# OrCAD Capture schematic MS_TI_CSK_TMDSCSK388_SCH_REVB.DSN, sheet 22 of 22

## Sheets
22 11.DM388 I/O PERIPHERALS: size C; title: DM388 I/O PERIPHERALS
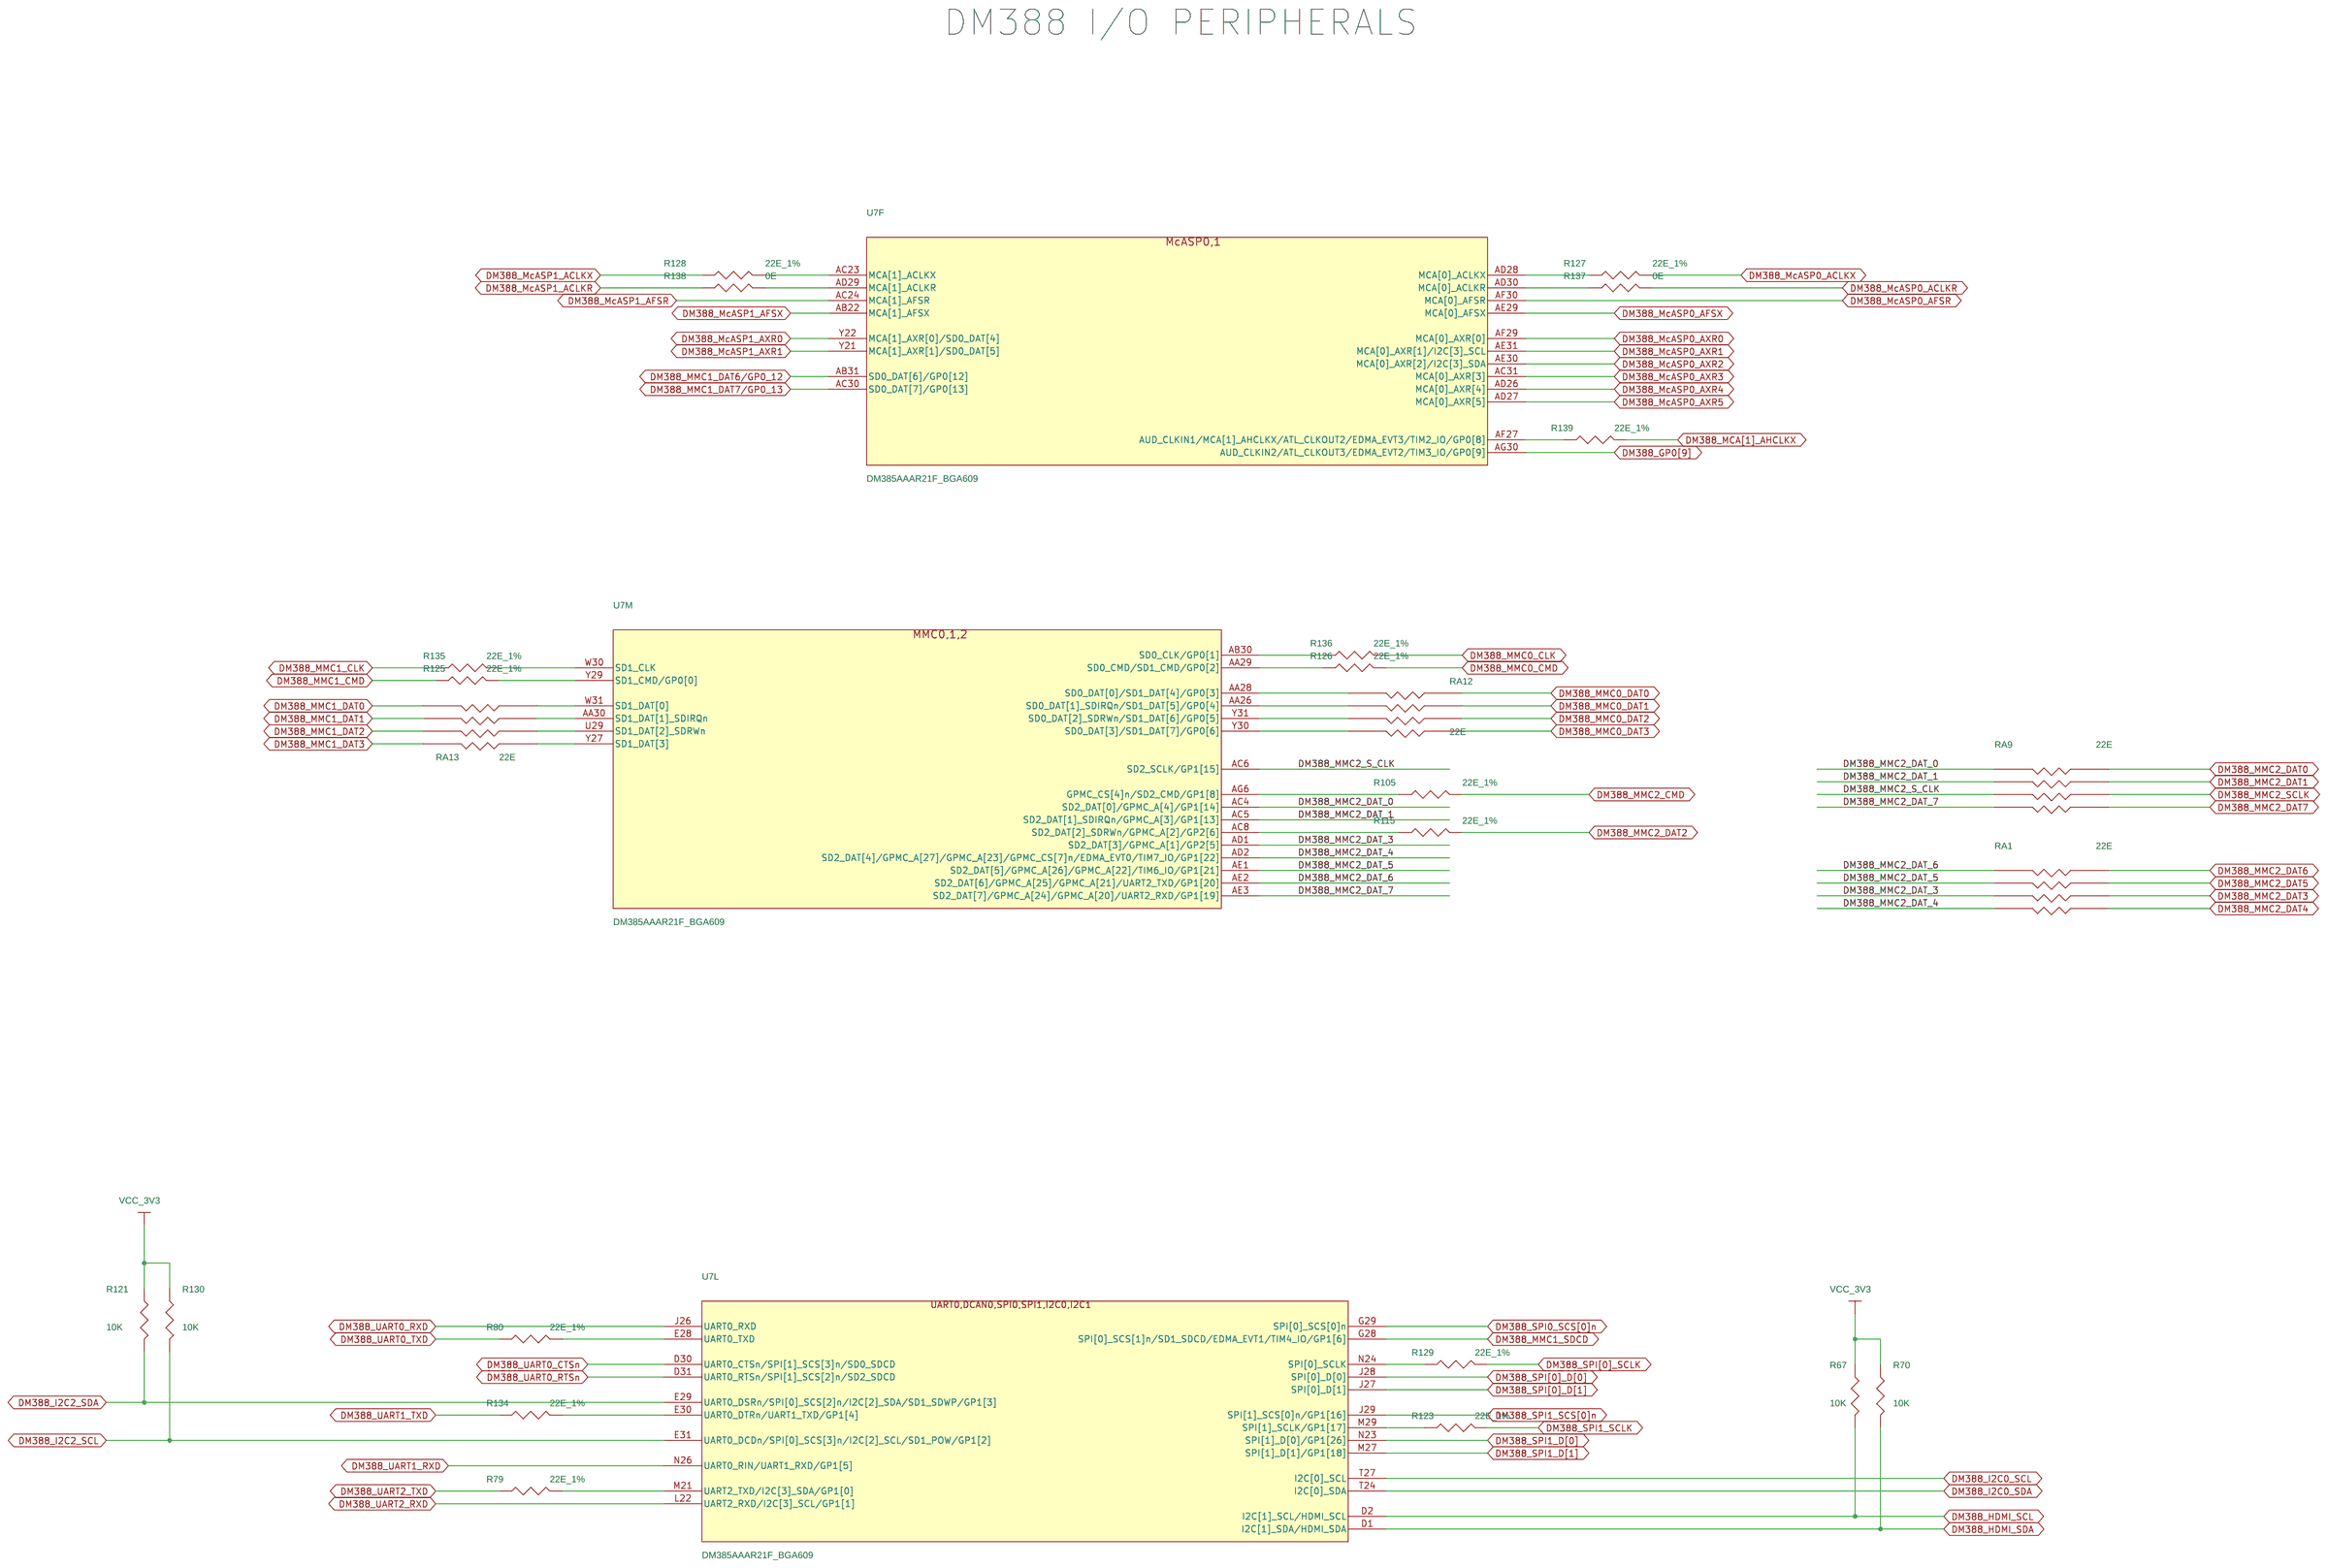
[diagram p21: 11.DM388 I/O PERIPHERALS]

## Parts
sheet 11.DM388 I/O PERIPHERALS
R67  10K  [RES0402]
R70  10K  [RES0402]
R79  22E_1%  [RES0402]
R80  22E_1%  [RES0402]
R105  22E_1%  [RES0402]
R115  22E_1%  [RES0402]
R121  10K  [RES0402]
R123  22E_1%  [RES0402]
R125  22E_1%  [RES0402]
R126  22E_1%  [RES0402]
R127  22E_1%  [RES0402]
R128  22E_1%  [RES0402]
R129  22E_1%  [RES0402]
R130  10K  [RES0402]
R134  22E_1%  [RES0402]
R135  22E_1%  [RES0402]
R136  22E_1%  [RES0402]
R137  0E  [RES0402]
R138  0E  [RES0402]
R139  22E_1%  [RES0402]
RA1  22E  [RESA_741X083_0402-4]
RA9  22E  [RESA_741X083_0402-4]
RA12  22E  [RESA_741X083_0402-4]
RA13  22E  [RESA_741X083_0402-4]
sheet 19.ETHERNET,HDMI & USB
U7  DM388AAAR21FP  [BGA609_19-68_635X635]  (sections A,B,C,D,E,F,G,H,I,J,K,L,M,N)

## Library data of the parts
R67 R70 R121 R130 = RESISTOR: RES 10K 1/16W 5% 0402; Alternate_mfr_name_A: AVX CORPORATION; Alternate_mfr_name_B: PANASONIC-ECG-ECG; Alternate_mfr_name_C: YAGEO AMERICA; Alternate_mfr_name_D: WALSIN; Alternate_mfr_part_number_A: CR05-103J-H; Alternate_mfr_part_number_B: ERJ-2GEJ103X; Alternate_mfr_part_number_C: 9C04021A1002JLHF3; Alternate_mfr_part_number_D: WR04X103_JT; Chkd/date: SHREESHAIL/061205; Crtd /date: MAZHAR/230805; Custom_Duty: 15%; Customs_HS_Code: 85332119; Distributor_name: DIGIKEY; Distributor_name_A: MOUSER; Distributor_name_B: DIGIKEY; Distributor_name_C: DIGIKEY; Distributor_name_D: NA; Distributor_part_number: 311-10KJRCT-ND; Distributor_part_number_A: 581-CR051002JT; Distributor_part_number_B: P10KJCT-ND; Distributor_part_number_C: 311-10KJCT-ND; Distributor_part_number_D: NA; Height: 0.40MM; Mfr_name: YAGEO AMERICA; Mfr_part_number: RC0402JR-0710KL; Mistral Part No: 110009030208-P; Package: 0402; Part_type: RESISTORS\FIXED; Project: HSE; RoHS: Pb-Free; Tolerance: 5%; Wattage: 1/16W; Datasheet: Y:\MIS_DATABASE\DATASHEETS\RESISTORS\YAGEO-RC0402.PDF
R79 R80 R105 R115 R123 R125-R129 R134-R136 R139 = RESISTOR: RES 22E 1/16W 1% 0402; Alternate_mfr_name_A: VISHAY; Alternate_mfr_part_number_A: CRCW040222R0FKED; Chkd/date: SUHAS/290910; Crtd /date: MAZHAR/090909; Cust_part_number: 4700-80047E; Custom_Duty: 15%; Customs_HS_Code: 85332119; Distributor_name: DIGIKEY; Distributor_name_A: DIGIKEY; Distributor_part_number: 311-22.0LRCT-ND; Distributor_part_number_A: 541-22.0LCT-ND; Height: 0.40MM; Mfr_name: YAGEO AMERICA; Mfr_part_number: RC0402FR-0722RL; Mistral Part No: 110009090004-P; Package: 0402; Part_type: RESISTORS\FIXED; Project: VMEFMCD; Remarks: In alternate datasheet it is RoHS COMPLIANT. Y:\MIS_DATABASE\DATASHEETS\RESISTORS\CRCW0402.PDF; RoHS: Pb-Free; Temperature: -55°C+155°C; Tolerance: 1%; Voltage: 50V; Wattage: 1/16W; Weight: 0.8g/1000pcs; Datasheet: Y:\MIS_DATABASE\DATASHEETS\RESISTORS\YAGEO-RC0402.PDF
R137 R138 = RESISTOR: RES 0K 1/16W 5% 0402; Chkd/date: USMAN240712; Crtd /date: CHAITHANYA/300911; Custom_Duty: 15%; Customs_HS_Code: 85332119; Distributor_name: DIGIKEY; Distributor_part_number: 311-0.0JRCT-ND; Height: 0.40MM; Mfr_name: YAGEO; Mfr_part_number: RC0402JR-070RL; Mistral Part No: 110011090036-R; Package: 0402; Part_type: RESISTORS\FIXED; Project: VP-4000-PROCESSOR; RoHS: RoHS; SIGNAL_MODEL: RESISTOR_RES0402_0E_0E; Temperature: -55°C+155°C; Tolerance: 5%; Voltage: NA; Wattage: 1/16W; Weight: NA; Datasheet: Y:\MIS_DATABASE\DATASHEETS\RESISTORS\YAGEO_RC0402JR.PDF
RA1 RA9 RA12 RA13 = RESARR_ISO4: RES ARRAY 4RES 22E 62.5mW 5% 0402; Chkd/date: VASANTHA/130516; Crtd /date: VASANTHA/130516; Distributor_name: DIGIKEY; Distributor_part_number: 741X083220JPCT-ND; Height: 0.50MM; Mfr_name: CTS; Mfr_part_number: 741X083220JP; Mistral Part No: 110016050004-R; Package: 0402; Part_type: RESISTORS\ARRAY; Project: TMDXCSK368; RoHS: RoHS; Temperature: -55°C+125°C; Tolerance: 5%; Voltage: NA; Wattage: 62.5mW; Weight: NA; Datasheet: Y:\MIS_DATABASE\DATASHEETS\RESISTORS\741C083.PDF
U7 = DM385AAAR21F_BGA609: IC PROCESSOR DIGITAL MEDIA FCBGA609; Chkd/date: VASANTHA/170516; Color: Default; Crtd /date: VASANTHA/170516; Custom_Duty: 15%; Customs_HS_Code: 85423100; Distributor_name: NA; Distributor_part_number: NA; Height: 1.32MM; Location X-Coordinate: 0; Location Y-Coordinate: 0; Mfr_name: TEXAS INSTRUMENTS; Mistral Part No: 141216050002-R; Package: FCBGA609; Part_type: ICS\DIGITAL\MICROPROCESSOR; Power Pins Visible: False; Primitive: DEFAULT; Project: TMDXCSK388; RoHS: RoHS; Temperature: 0°C+95°C; Tolerance: NA; Voltage: NA; Wattage: NA; Weight: NA; Datasheet: Y:\MIS_DATABASE\DATASHEETS\ICS\DIGITAL\MICROCONTROLLER\DM385-88.PDF

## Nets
VCC_3V3: R67.1 R70.1 R121.1 R130.1 ; also on sheet 9 10 12 13 14 16 17 18 19 21
DM388_GP0[9]: U7.AG30(AUD_CLKIN2/ATL_CLKOUT3/EDMA_EVT2/TIM3_IO/GP0[9]) ; also on sheet 21
DM388_HDMI_SCL: R67.2 U7.D2(I2C[1]_SCL/HDMI_SCL) ; also on sheet 21
DM388_HDMI_SDA: R70.2 U7.D1(I2C[1]_SDA/HDMI_SDA) ; also on sheet 21
DM388_I2C0_SCL: U7.T27(I2C[0]_SCL) ; also on sheet 17
DM388_I2C0_SDA: U7.T24(I2C[0]_SDA) ; also on sheet 17
DM388_I2C2_SCL: R130.2 U7.E31(UART0_DCDn/SPI[0]_SCS[3]n/I2C[2]_SCL/SD1_POW/GP1[2]) ; also on sheet 21
DM388_I2C2_SDA: R121.2 U7.E29(UART0_DSRn/SPI[0]_SCS[2]n/I2C[2]_SDA/SD1_SDWP/GP1[3]) ; also on sheet 21
DM388_MCA[1]_AHCLKX: R139.2 ; also on sheet 21
DM388_McASP0_ACLKR: R137.2 ; also on sheet 21
DM388_McASP0_ACLKX: R127.2 ; also on sheet 12
DM388_McASP0_AFSR: U7.AF30(MCA[0]_AFSR) ; also on sheet 21
DM388_McASP0_AFSX: U7.AE29(MCA[0]_AFSX) ; also on sheet 12
DM388_McASP0_AXR0: U7.AF29(MCA[0]_AXR[0]) ; also on sheet 12
DM388_McASP0_AXR1: U7.AE31(MCA[0]_AXR[1]/I2C[3]_SCL) ; also on sheet 12
DM388_McASP0_AXR2: U7.AE30(MCA[0]_AXR[2]/I2C[3]_SDA) ; also on sheet 21
DM388_McASP0_AXR3: U7.AC31(MCA[0]_AXR[3]) ; also on sheet 21
DM388_McASP0_AXR4: U7.AD26(MCA[0]_AXR[4]) ; also on sheet 21
DM388_McASP0_AXR5: U7.AD27(MCA[0]_AXR[5]) ; also on sheet 21
DM388_McASP1_ACLKR: R138.1 ; also on sheet 21
DM388_McASP1_ACLKX: R128.1 ; also on sheet 21
DM388_McASP1_AFSR: U7.AC24(MCA[1]_AFSR) ; also on sheet 21
DM388_McASP1_AFSX: U7.AB22(MCA[1]_AFSX) ; also on sheet 21
DM388_McASP1_AXR0: U7.Y22(MCA[1]_AXR[0]/SD0_DAT[4]) ; also on sheet 21
DM388_McASP1_AXR1: U7.Y21(MCA[1]_AXR[1]/SD0_DAT[5]) ; also on sheet 21
DM388_MMC0_CLK: R136.2 ; also on sheet 12
DM388_MMC0_CMD: R126.2 ; also on sheet 12
DM388_MMC0_DAT0: RA12.4 ; also on sheet 12
DM388_MMC0_DAT1: RA12.3 ; also on sheet 12
DM388_MMC0_DAT2: RA12.2 ; also on sheet 12
DM388_MMC0_DAT3: RA12.1 ; also on sheet 12
DM388_MMC1_CLK: R135.1 ; also on sheet 21
DM388_MMC1_CMD: R125.1 ; also on sheet 21
DM388_MMC1_DAT0: RA13.5 ; also on sheet 21
DM388_MMC1_DAT1: RA13.6 ; also on sheet 21
DM388_MMC1_DAT2: RA13.7 ; also on sheet 21
DM388_MMC1_DAT3: RA13.8 ; also on sheet 21
DM388_MMC1_DAT6/GP0_12: U7.AB31(SD0_DAT[6]/GP0[12]) ; also on sheet 21
DM388_MMC1_DAT7/GP0_13: U7.AC30(SD0_DAT[7]/GP0[13]) ; also on sheet 21
DM388_MMC1_SDCD: U7.G28(SPI[0]_SCS[1]n/SD1_SDCD/EDMA_EVT1/TIM4_IO/GP1[6]) ; also on sheet 21
DM388_MMC2_CMD: R105.2 ; also on sheet 21
DM388_MMC2_DAT0: RA9.4 ; also on sheet 21
DM388_MMC2_DAT1: RA9.3 ; also on sheet 21
DM388_MMC2_DAT2: R115.2 ; also on sheet 21
DM388_MMC2_DAT3: RA1.2 ; also on sheet 21
DM388_MMC2_DAT4: RA1.1 ; also on sheet 21
DM388_MMC2_DAT5: RA1.3 ; also on sheet 21
DM388_MMC2_DAT6: RA1.4 ; also on sheet 21
DM388_MMC2_DAT7: RA9.1 ; also on sheet 21
DM388_MMC2_DAT_0: RA9.5 U7.AC4(SD2_DAT[0]/GPMC_A[4]/GP1[14])
DM388_MMC2_DAT_1: RA9.6 U7.AC5(SD2_DAT[1]_SDIRQn/GPMC_A[3]/GP1[13])
DM388_MMC2_DAT_3: RA1.7 U7.AD1(SD2_DAT[3]/GPMC_A[1]/GP2[5])
DM388_MMC2_DAT_4: RA1.8 U7.AD2(SD2_DAT[4]/GPMC_A[27]/GPMC_A[23]/GPMC_CS[7]n/EDMA_EVT0/TIM7_IO/GP1[22])
DM388_MMC2_DAT_5: RA1.6 U7.AE1(SD2_DAT[5]/GPMC_A[26]/GPMC_A[22]/TIM6_IO/GP1[21])
DM388_MMC2_DAT_6: RA1.5 U7.AE2(SD2_DAT[6]/GPMC_A[25]/GPMC_A[21]/UART2_TXD/GP1[20])
DM388_MMC2_DAT_7: RA9.8 U7.AE3(SD2_DAT[7]/GPMC_A[24]/GPMC_A[20]/UART2_RXD/GP1[19])
DM388_MMC2_S_CLK: RA9.7 U7.AC6(SD2_SCLK/GP1[15])
DM388_MMC2_SCLK: RA9.2 ; also on sheet 21
DM388_SPI0_SCS[0]n: U7.G29(SPI[0]_SCS[0]n) ; also on sheet 21
DM388_SPI1_D[0]: U7.N23(SPI[1]_D[0]/GP1[26]) ; also on sheet 21
DM388_SPI1_D[1]: U7.M27(SPI[1]_D[1]/GP1[18]) ; also on sheet 21
DM388_SPI1_SCLK: R123.2 ; also on sheet 21
DM388_SPI1_SCS[0]n: U7.J29(SPI[1]_SCS[0]n/GP1[16]) ; also on sheet 21
DM388_SPI[0]_D[0]: U7.J28(SPI[0]_D[0]) ; also on sheet 21
DM388_SPI[0]_D[1]: U7.J27(SPI[0]_D[1]) ; also on sheet 21
DM388_SPI[0]_SCLK: R129.2 ; also on sheet 21
DM388_UART0_CTSn: U7.D30(UART0_CTSn/SPI[1]_SCS[3]n/SD0_SDCD) ; also on sheet 21
DM388_UART0_RTSn: U7.D31(UART0_RTSn/SPI[1]_SCS[2]n/SD2_SDCD) ; also on sheet 21
DM388_UART0_RXD: U7.J26(UART0_RXD) ; also on sheet 21
DM388_UART0_TXD: R80.1 ; also on sheet 21
DM388_UART1_RXD: U7.N26(UART0_RIN/UART1_RXD/GP1[5]) ; also on sheet 21
DM388_UART1_TXD: R134.1 ; also on sheet 21
DM388_UART2_RXD: U7.L22(UART2_RXD/I2C[3]_SCL/GP1[1]) ; also on sheet 12
DM388_UART2_TXD: R79.1 ; also on sheet 12
N14567220: R136.1 U7.AB30(SD0_CLK/GP0[1])
N14567296: R135.2 U7.W30(SD1_CLK)
N14568444: R127.1 U7.AD28(MCA[0]_ACLKX)
N14568464: R128.2 U7.AC23(MCA[1]_ACLKX)
N14568476: R139.1 U7.AF27(AUD_CLKIN1/MCA[1]_AHCLKX/ATL_CLKOUT2/EDMA_EVT3/TIM2_IO/GP0[8])
N14776629: R138.2 U7.AD29(MCA[1]_ACLKR)
N14776712: R137.1 U7.AD30(MCA[0]_ACLKR)
N14776785: R129.1 U7.N24(SPI[0]_SCLK)
N14776789: R123.1 U7.M29(SPI[1]_SCLK/GP1[17])
N14783196: RA13.4 U7.W31(SD1_DAT[0])
N14783200: RA13.3 U7.AA30(SD1_DAT[1]_SDIRQn)
N14783204: RA13.2 U7.U29(SD1_DAT[2]_SDRWn)
N14783208: RA13.1 U7.Y27(SD1_DAT[3])
N15102842: R79.2 U7.M21(UART2_TXD/I2C[3]_SDA/GP1[0])
N15102865: R134.2 U7.E30(UART0_DTRn/UART1_TXD/GP1[4])
N15102869: R80.2 U7.E28(UART0_TXD)
N15123588: R125.2 U7.Y29(SD1_CMD/GP0[0])
N15123674: R126.1 U7.AA29(SD0_CMD/SD1_CMD/GP0[2])
N15123798: RA12.5 U7.AA28(SD0_DAT[0]/SD1_DAT[4]/GP0[3])
N15123807: RA12.6 U7.AA26(SD0_DAT[1]_SDIRQn/SD1_DAT[5]/GP0[4])
N15123817: RA12.7 U7.Y31(SD0_DAT[2]_SDRWn/SD1_DAT[6]/GP0[5])
N15123828: RA12.8 U7.Y30(SD0_DAT[3]/SD1_DAT[7]/GP0[6])
N15124532: R105.1 U7.AG6(GPMC_CS[4]n/SD2_CMD/GP1[8])
N15266407: R115.1 U7.AC8(SD2_DAT[2]_SDRWn/GPMC_A[2]/GP2[6])

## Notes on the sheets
sheet 22
- DM388 I/O PERIPHERALS
